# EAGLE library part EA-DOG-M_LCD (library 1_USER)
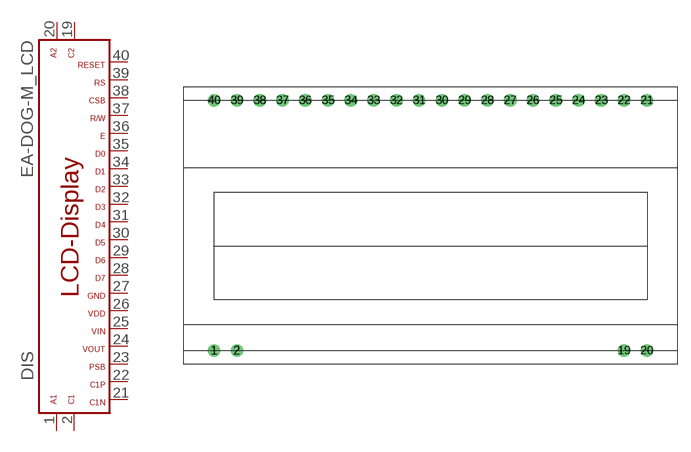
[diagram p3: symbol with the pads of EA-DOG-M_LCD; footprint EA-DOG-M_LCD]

Designator prefix DIS

## EA-DOG-M_LCD  [EA-DOG-M_LCD]
1  1  pas
2  2  pas
19  19  pas
20  20  pas
21  21
22  22
23  23
24  24
25  25
26  26  pwr
27  27  pwr
28  28
29  29
30  30
31  31
32  32
33  33
34  34
35  35
36  36
37  37
38  38
39  39
40  40

## Footprint EA-DOG-M_LCD (pad centres in mm)
drill 0.9 round: 1 -24.13,-27.94; 2 -21.59,-27.94; 19 21.59,-27.94; 20 24.13,-27.94; 21 24.13,0; 22 21.59,0; 23 19.05,0; 24 16.51,0; 25 13.97,0; 26 11.43,0; 27 8.89,0; 28 6.35,0; 29 3.81,0; 30 1.27,0; 31 -1.27,0; 32 -3.81,0; 33 -6.35,0; 34 -8.89,0; 35 -11.43,0; 36 -13.97,0; 37 -16.51,0; 38 -19.05,0; 39 -21.59,0; 40 -24.13,0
